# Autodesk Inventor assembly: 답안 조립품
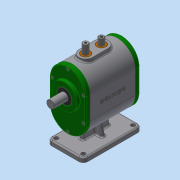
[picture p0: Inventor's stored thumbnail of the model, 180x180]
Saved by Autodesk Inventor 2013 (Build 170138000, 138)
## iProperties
Created: 2018-10
Part Number: 답안 조립품
Document SubType Name: Assembly
Designer: Administrator
Author: Administrator
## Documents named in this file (15)
- C:\Users\Administrator\Desktop\381007V1030\답안 조립품.iam
- C:\Users\Administrator\Desktop\381007V1030\본체.ipt
- C:\Users\Administrator\Desktop\381007V1030\가변 스프링.ipt
- C:\Users\Administrator\Desktop\381007V1030\뒤커버.ipt
- C:\Users\Administrator\Desktop\381007V1030\메인축.ipt
- C:\Users\Administrator\Desktop\381007V1030\베어링 608.ipt
- C:\Users\Administrator\Desktop\381007V1030\베어링 6003.ipt
- C:\Users\Administrator\Desktop\381007V1030\볼트 M4.ipt
- C:\Users\Administrator\Desktop\381007V1030\부시.ipt
- C:\Users\Administrator\Desktop\381007V1030\서브축.ipt
- C:\Users\Administrator\Desktop\381007V1030\슬라이더.ipt
- C:\Users\Administrator\Desktop\381007V1030\앞커버.ipt
- C:\Users\Administrator\Desktop\381007V1030\오일실 8 22 7.ipt
- C:\Users\Administrator\Desktop\381007V1030\오일실 17 32 8.ipt
- C:\Users\Administrator\Desktop\381007V1030\가변 스프링-2.ipt
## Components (2 placed, 2 different names)
1. 가변 스프링:1
2. 가변 스프링-2:1
